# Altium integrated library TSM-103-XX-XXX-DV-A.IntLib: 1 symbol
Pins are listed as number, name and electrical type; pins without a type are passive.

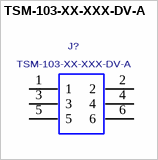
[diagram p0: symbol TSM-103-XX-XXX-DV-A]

## TSM-103-XX-XXX-DV-A
designator J?
Terminal Strip, Dual Row Vertical, Surface Mount, 0.100" Pitch, 6 Pins.; MANUFACTURER: SAMTEC
footprint TSM-103-XX-XXX-DV-A
pins: 1, 2, 3, 4, 5, 6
